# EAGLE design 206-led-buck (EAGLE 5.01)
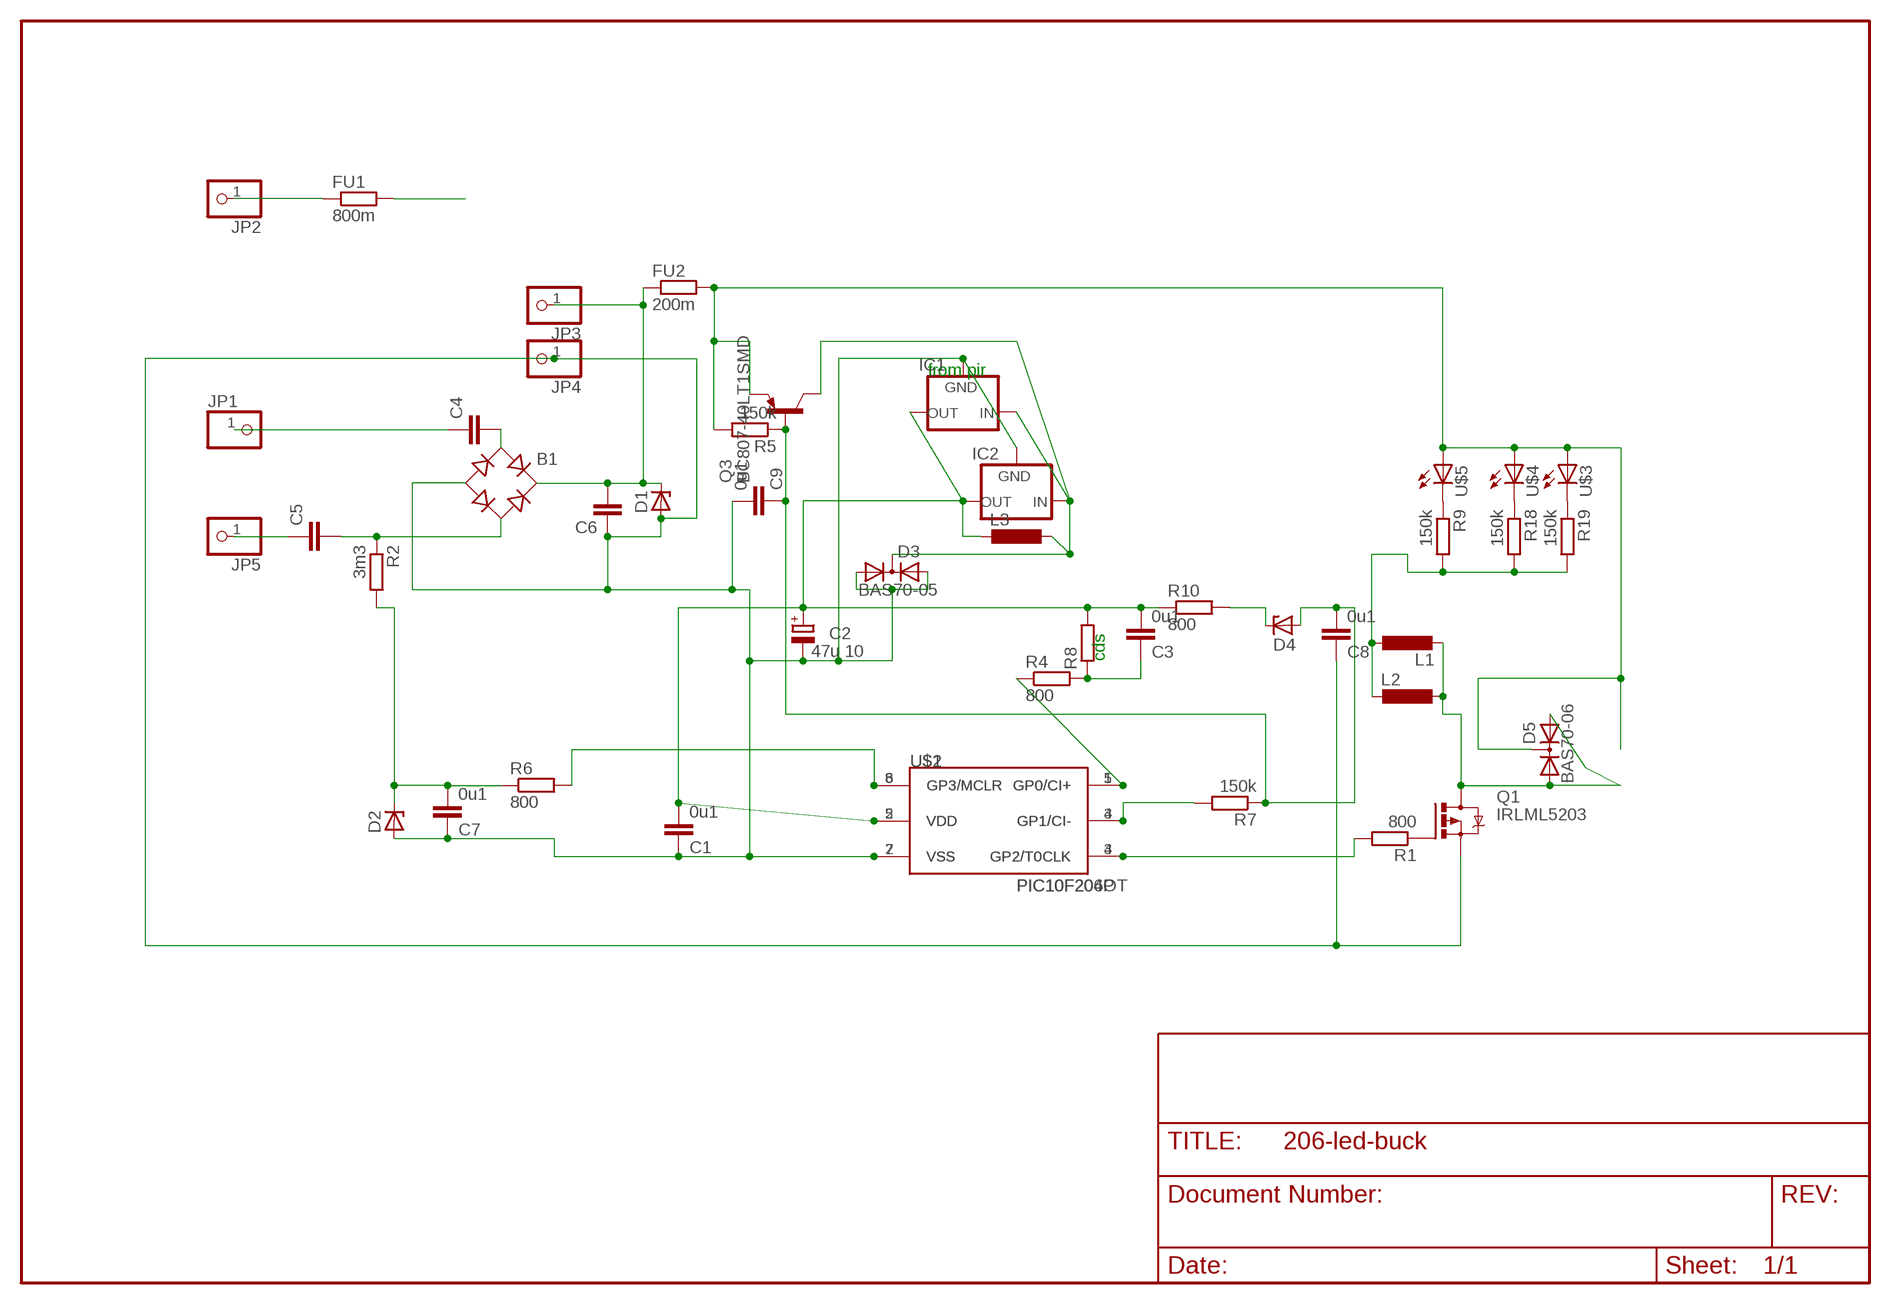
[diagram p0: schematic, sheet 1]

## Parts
B1  RB1A  [RB1A]
C1  0u1  C-EUC1206  [C1206]
C2  47u 10  CPOL-EUE2.5-5  [E2,5-5]
C3  0u1  C-EUC1206  [C1206]
C4  C-EU050-025X075  [C050-025X075]
C5  C-EU050-025X075  [C050-025X075]
C6  C-EU050-025X075  [C050-025X075]
C7  0u1  C-EUC1206  [C1206]
C8  0u1  C-EUC1206  [C1206]
C9  0u1  C-EUC1206  [C1206]
D1  ZENER-DIODEZD-7.5  [ZDIO-7.5]
D2  ZENER-DIODESOT23  [SOT23]
D3  BAS70-05  [SOT23]
D4  ZENER-DIODESOT23  [SOT23]
D5  BAS70-06  [SOT23]
FU1  800m  R-EU_0204/5  [0204/5]
FU2  200m  R-EU_0204/5  [0204/5]
IC1  XC63FPT  [TO92]
IC2  XC63FPP  [SOT89R]
JP1  PINHD-1X1  [1X01]
JP2  PINHD-1X1  [1X01]
JP3  PINHD-1X1  [1X01]
JP4  PINHD-1X1  [1X01]
JP5  PINHD-1X1  [1X01]
L1  L-EUL5650M  [L5650M]
L2  L-EU0207/7  [0207/7]
L3  L-EU0204V  [0204V]
Q1  IRLML5203  [MICRO3]
Q3  BC807-40LT1SMD  [SOT23-BEC]
R1  800  R-EU_R1206  [R1206]
R2  3m3  R-EU_R1206  [R1206]
R4  800  R-EU_R1206  [R1206]
R5  150k  R-EU_R1206  [R1206]
R6  800  R-EU_R1206  [R1206]
R7  150k  R-EU_R1206  [R1206]
R8  R-EU_0207/5V  [0207/5V]
R9  150k  R-EU_R1206  [R1206]
R10  800  R-EU_R1206  [R1206]
R18  150k  R-EU_R1206  [R1206]
R19  150k  R-EU_R1206  [R1206]
U$1  PIC10F206P  [DIL8]
U$2  PIC10F204OT  [SOT23-6]
U$3  LED5MM  [LED5MM]
U$4  LED5MM  [LED5MM]
U$5  LED5MM  [LED5MM]

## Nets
GND: B1.- C1.1 C2.- C6.1 C7.1 C8.1 C9.2 D1.A D2.1(A) D3.1(A1) D3.2(A2) IC1.1(GND) IC2.1(GND) JP4.1 Q1.2(S) U$1.7(VSS) U$2.2(VSS)
N$1: B1.+ C6.2 D1.C FU2.1 JP3.1
N$4: FU1.1 JP2.1
N$6: D4.3(C) R10.2
N$7: D5.3(C) FU2.2 Q3.E R5.2 U$3.A U$4.A U$5.A
N$8: C8.2 C9.1 D4.1(A) Q3.B R5.1 R7.1
N$9: FU1.2
N$10: Q1.1(G) R1.1
N$12: R6.2 U$1.8(GP3/MCLR) U$2.6(GP3/MCLR)
N$13: R7.2 U$1.4(GP1/CI-) U$2.3(GP1/CI-)
N$14: R1.2 U$1.3(GP2/T0CLK) U$2.4(GP2/T0CLK)
N$15: D3.3(C) IC1.2(IN) IC2.2(IN) L3.1 Q3.C
N$16: C7.2 D2.3(C) R2.2 R6.1
N$17: C5.1 JP5.1
N$18: B1.AC2 C5.2 R2.1
N$20: C4.1 JP1.1
N$22: L1.1 L2.2 R9.2 R18.2 R19.2
N$23: C3.1 R4.2 R8.1
N$26: D5.1(A1) D5.2(A2) L1.2 L2.1 Q1.3(D)
N$29: R4.1 U$1.5(GP0/CI+) U$2.1(GP0/CI+)
N$33: B1.AC1 C4.2
N$38: R9.1 U$5.K(C)
N$54: R18.1 U$4.K(C)
N$55: R19.1 U$3.K(C)
V2CC: C1.2 C2.+ C3.2 IC1.3(OUT) IC2.3(OUT) L3.2 R8.2 R10.1 U$1.2(VDD) U$2.5(VDD)

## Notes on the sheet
- from pir
- cds

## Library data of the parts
B1 = rectifier:RB1A: RECTIFIER 1 A
C1 C3-C9 = rcl:C-EU: CAPACITOR, European symbol
C2 = rcl:CPOL-EU: POLARIZED CAPACITOR, European symbol
D1 D2 D4 = diode-1:ZENER-DIODE: Z-Diode
D3 = diode-1:BAS70-05: Silicon Schottky Diodes General-purpose diode for high-speed switching
D5 = diode-1:BAS70-06: Silicon Schottky Diodes General-purpose diode for high-speed switching
FU1 FU2 R1 R2 R4-R7 R9 R10 R18 R19 = rcl:R-EU_: RESISTOR, European symbol
IC1 IC2 = v-reg:XC63FP: Positiv Voltage Regulators www.torex.co.jp/english/product/pro02/pdf/0201_xc62fp.pdf
JP1-JP5 = pinhead:PINHD-1X1: PIN HEADER
L1 = rcl-2:L-EU: INDUCTOR, European symbol
L2 L3 = rcl:L-EU: INDUCTOR, European symbol
Q1 = transistor-power:IRLML5203: HEXFET P-Channel Power MOSFET
Q3 = transistor-pnp:BC807*: PNP Transistror
R8 = rcl(2):R-EU_: RESISTOR, European symbol
U$1 U$2 = microchip-3:PIC10F2*: uPC nW 0,25/0,5k Program Flash memory Comparator
U$3-U$5 = led(3):LED: LED

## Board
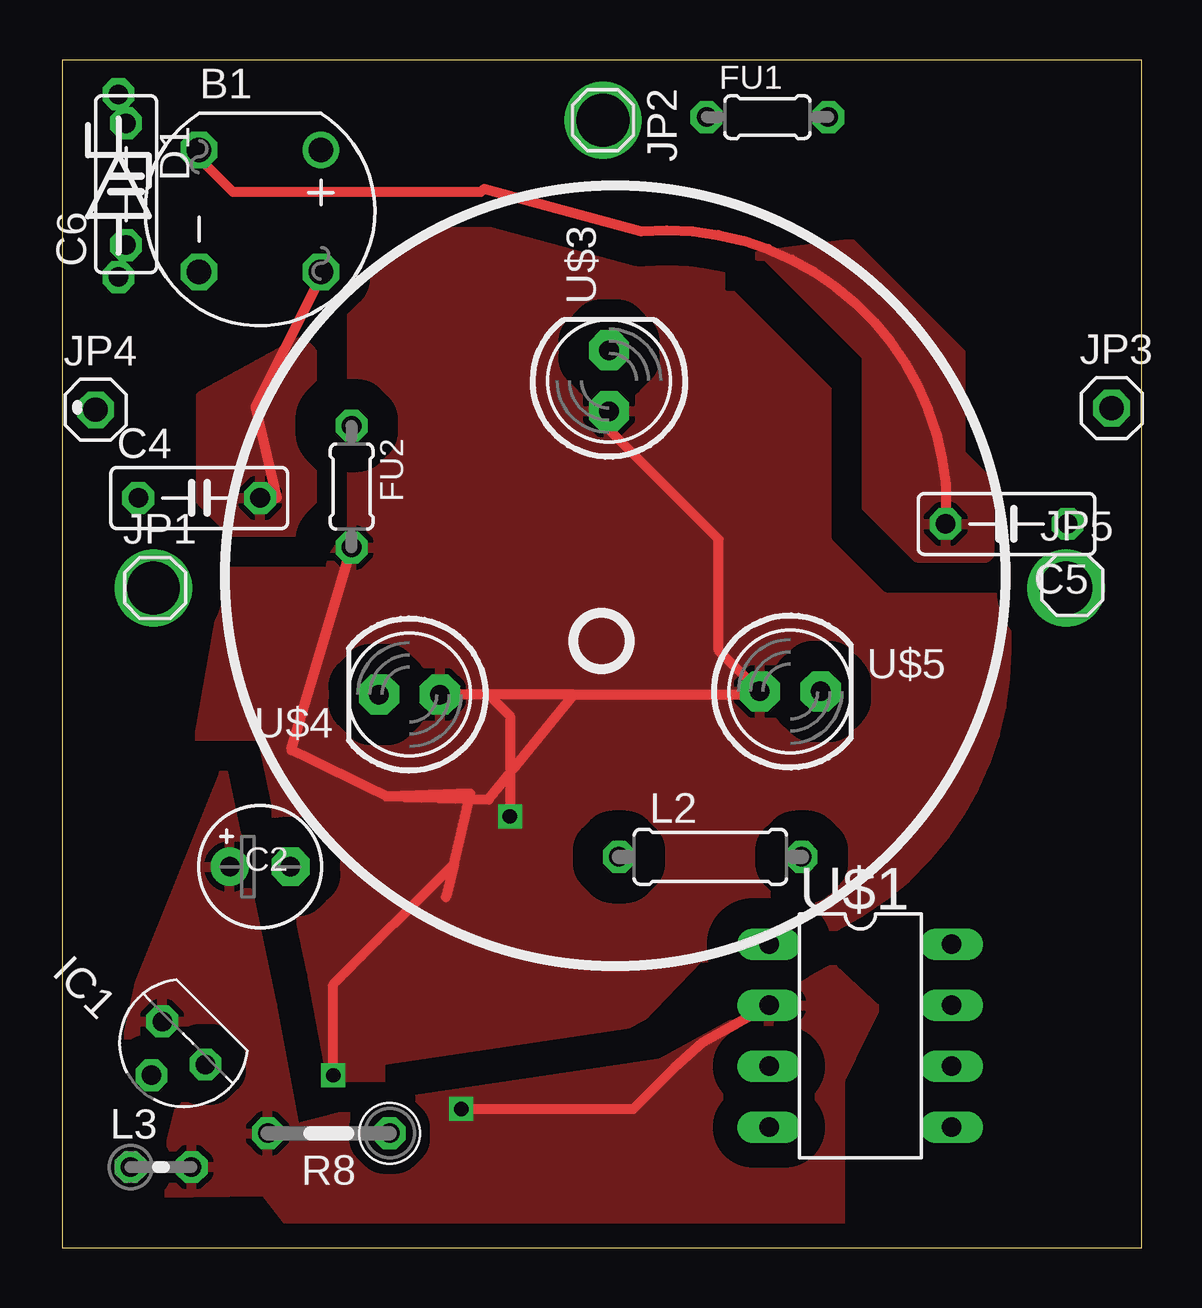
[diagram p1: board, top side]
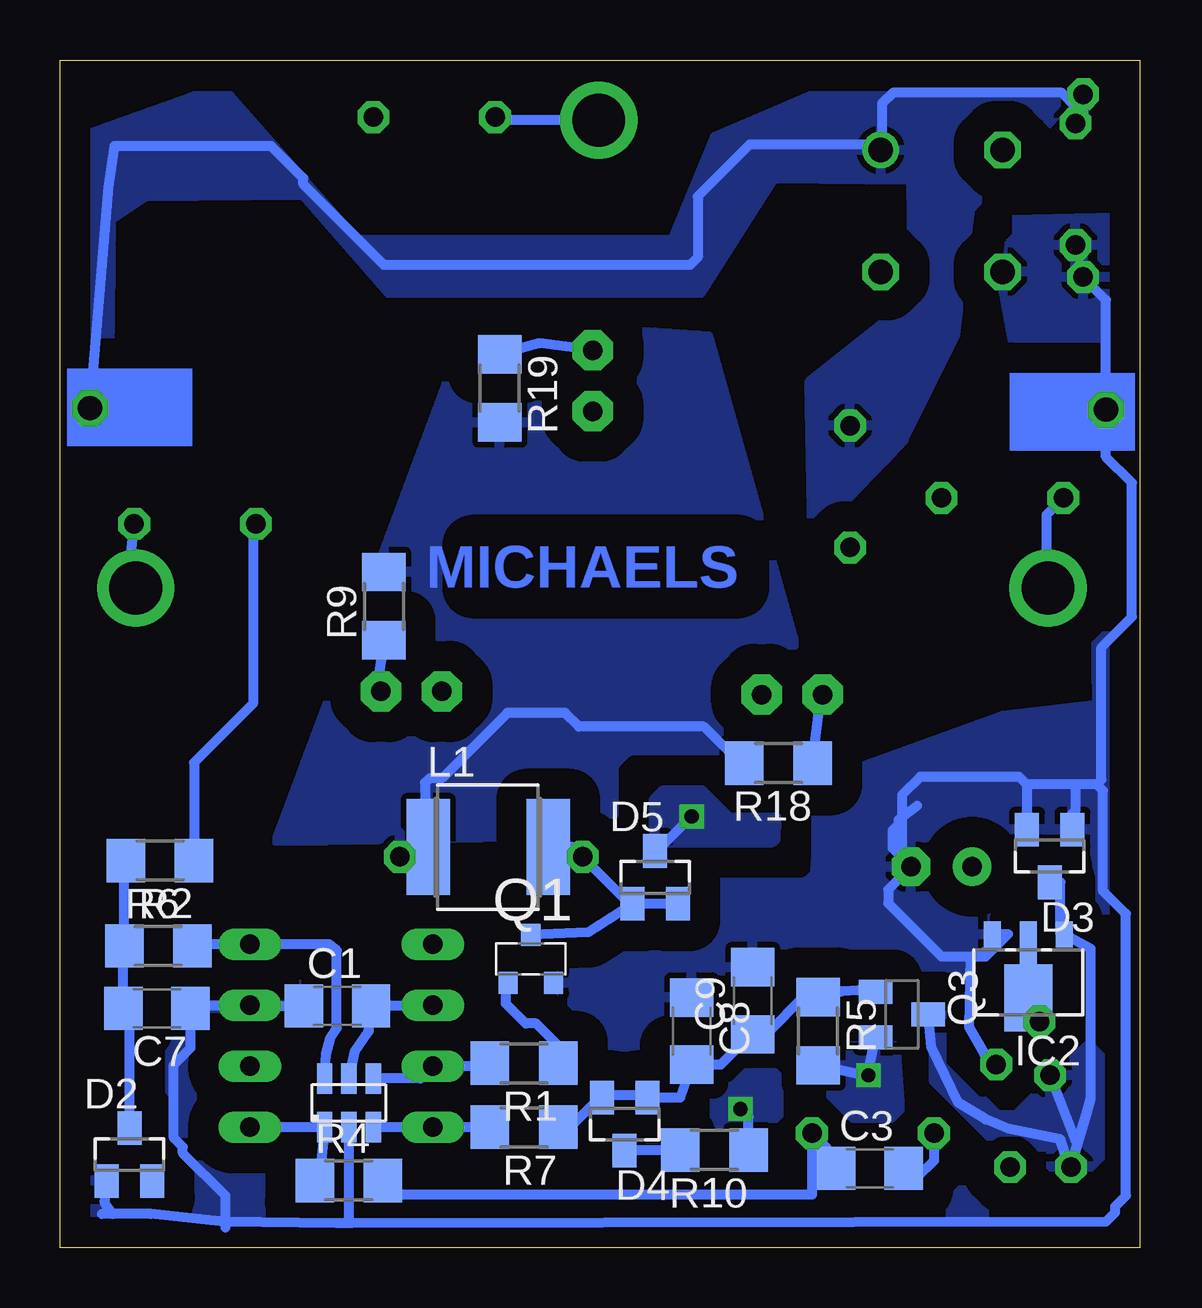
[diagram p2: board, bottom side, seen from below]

Size 45 x 49.5 mm. Coordinates in mm from the lower left corner, seen from the top.
Outline: 0,0 45,0 45,49.5 0,49.5 0,0
Copper layers (1*16): Top 0.035mm / dielectric 1.5mm / Bottom 0.035mm
Design rules "default": minimum track width 10mil, minimum drill 24mil, track to track 8mil, track to pad 8mil, pad to pad 8mil, via to via 8mil, smd to smd 8mil, copper to edge 40mil, drill to drill 8mil, minimum pad ring 10mil, minimum via ring 8mil, stop-mask expansion 4mil, vias tented up to drill 0mil, thermal gap 10mil

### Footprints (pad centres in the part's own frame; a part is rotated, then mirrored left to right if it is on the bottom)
RB1A = drill 1.016 round: + -2.54,2.54 | drill 1.016 octagon: - 2.54,-2.54; AC1 2.54,2.54; AC2 -2.54,-2.54
C1206 = smd 1.6 x 1.8: 1 -1.4,0; 2 1.4,0
E2,5-5 = drill 0.813 pad 1.6 round: + -1.27,0 | drill 0.813 pad 1.6 octagon: - 1.27,0
C050-025X075 = drill 0.813 octagon: 1 -2.54,0; 2 2.54,0
ZDIO-7.5 = drill 0.813 octagon: A 3.81,0; C -3.81,0
SOT23 = smd 1 x 1.4: 1 -0.95,-1.1; 2 0.95,-1.1; 3 0,1.1
0204/5 = drill 0.813 octagon: 1 -2.54,0; 2 2.54,0
TO92 = drill 0.813 octagon: 1 -1.27,0; 2 0,1.905; 3 1.27,0
SOT89R = smd 0.7 x 1.1: 1 1.5,-1.75; 2 -1.5,-1.75 | smd 0.7 x 1.8: 3 0,-1.4 | smd 2 x 2.8: 4 0,0.9
1X01 = drill 1.016 octagon: 1 0,0
L5650M = smd 1.8 x 4: 1 -2.5,0; 2 2.5,0
0207/7 = drill 0.813 octagon: 1 -3.81,0; 2 3.81,0
0204V = drill 0.813 octagon: 1 -1.27,0; 2 1.27,0
MICRO3 = smd 0.8 x 0.9: 1 -0.95,-1; 2 0.95,-1; 3 0,1
SOT23-BEC = smd 1 x 1.4: B -0.95,-1.1; C 0,1.1; E 0.95,-1.1
R1206 = smd 1.6 x 1.803: 1 -1.422,0; 2 1.422,0
0207/5V = drill 0.813 octagon: 1 -2.54,0; 2 2.54,0
DIL8 = drill 0.813 long: 1 -3.81,-3.81; 2 -1.27,-3.81; 3 1.27,-3.81; 4 3.81,-3.81; 5 3.81,3.81; 6 1.27,3.81; 7 -1.27,3.81; 8 -3.81,3.81
SOT23-6 = smd 0.635 x 1.27: 1 -1.016,-1.016; 2 0,-1.016; 3 1.016,-1.016; 4 1.016,1.016; 5 0,1.016; 6 -1.016,1.016
LED5MM = drill 0.813 pad 1.676 octagon: A -1.27,0; K 1.27,0

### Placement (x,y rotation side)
B1  8.25,43.21 270 top
C1  33.43,10.08 0 bottom
C2  8.26,15.88 0 top
C3  11.24,3.3 0 bottom
C4  5.71,31.24 0 top
C5  39.37,30.16 180 top
C6  2.67,44.32 90 top
C7  40.96,9.97 180 bottom
C8  18.67,9.02 270 bottom
C9  16.13,10.29 90 bottom
D1  2.35,44.26 270 top
D2  42.1,3.87 0 bottom
D3  3.75,16.32 180 bottom
D4  21.46,5.14 180 bottom
D5  20.19,15.43 0 bottom
FU1  29.4,47.12 0 top
FU2  12.07,31.72 270 top
IC1  5.07,8.53 135 top
IC2  4.64,11.3 180 bottom
JP1  3.87,27.5 0 top
JP2  22.54,46.99 270 top
JP3  43.75,34.99 0 top
JP4  1.4,34.92 0 top
JP5  42.1,27.62 0 top
L1  27.15,16.69 0 bottom
L2  27.02,16.29 0 top
L3  4.13,3.35 0 top
Q1  25.38,12.03 0 bottom
Q3  9.91,9.72 270 bottom
R1  25.65,7.68 180 bottom
R2  40.83,16.13 180 bottom
R4  32.96,2.79 0 bottom
R5  13.4,9.02 270 bottom
R6  40.89,12.57 0 bottom
R7  25.65,5.02 180 bottom
R8  11.11,4.76 180 top
R9  31.5,26.73 90 bottom
R10  17.72,4.06 180 bottom
R18  15.05,20.19 180 bottom
R19  26.67,35.81 270 bottom
U$1  33.27,8.83 270 top
U$2  32.96,6.03 0 bottom
U$3  22.8,36.13 90 top
U$4  14.48,23.05 180 top
U$5  30.35,23.18 0 top

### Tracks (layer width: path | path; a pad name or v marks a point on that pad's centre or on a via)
GND
  Bottom 0.406: 42.8,1.4 43.13,1.84 D2.1 | 42.8,1.4 43.24,1.4 | 38.16,1.08 33.47,1.02 32.96,1.02 | 38.16,1.08 41.21,1.4 42.8,1.4 | 38.16,1.08 38.1,0.83 38.1,2.16 39.88,3.94 39.88,4.19 40.26,4.57 40.26,7.62 39.56,8.32 C7.1 39.43,10.1 U$1.7 37.06,10.07 C1.1 | IC1.1 6.48,8.07 7.11,9.21 7.05,12.13 | 7.05,12.13 6.03,12.51 6.11,12.45 IC2.1 5.49,13.05 6.41,12.13 7.05,12.13 | 9.27,18.41 10.03,17.84 10.03,17.65 10.29,17.4 10.29,16.64 C2.- | D3.1 2.8,18.09 2.67,18.22 2.67,19.24 2.73,19.3 | 4.7,19.3 D3.2 | 4.7,19.3 5.02,19.62 9.14,19.62 9.91,18.86 9.91,16.26 C2.- | 7.05,12.13 8.26,12.13 10.48,14.35 10.48,14.92 C2.- | 1.78,19.3 2.73,19.3 | 2.73,19.3 4.69,19.3 4.7,19.3 | D1.A 1.4,39.5 JP4.1 1.4,32.96 0.32,31.88 0.32,26.29 1.59,25.02 1.59,19.49 1.78,19.3 | 1.78,19.3 1.52,19.05 1.52,14.86 0.57,13.91 0.57,2.16 1.02,1.71 1.02,1.46 1.4,1.08 32.83,1.02 32.96,1.02 | 32.96,1.02 U$2.2
  pour Bottom (isolate 1.27, rank 5): 0.95,42.93 6.22,42.8 5.21,37.27 1.91,33.02 1.78,22.61 5.71,22.16 13.97,19.18 35.5,17.34 35.43,20.38 45.02,20.26 44.64,0.32 -0.06,0.25
N$1
  Bottom 0.406: JP3.1 42.99,44.2 42.74,45.91 36.2,45.91 34.86,44.58 34.86,44.32 31.5,40.96 18.73,40.96 18.41,41.27 18.41,43.81 16.26,45.97 11.2,45.97 B1.+ 10.73,45.8 10.73,47.69 10.29,48.13 3.24,48.13 2.67,47.56 C6.2 2.35,47.18 D1.C
  pour Bottom (isolate 1.27, rank 2): 1.52,49.34 9.97,49.59 17.72,46.29 19.49,42 32.64,42 38.29,48.39 44.89,46.04 44.7,36.96 42.93,37.08 42.86,42.86 41.4,43.81 34.86,43.88 31.31,39.8 18.29,39.8 15.24,44.58 9.53,44.51 9.46,39.5 13.78,36.07 13.65,29.65 10.67,32.77 9.84,33.66 7.68,38.04 7.05,43.31
N$2  (via drill 2.2)
  other vias: 3.81,27.5
N$3  (via drill 2.2)
  other vias: 41.85,27.5
N$4
  Bottom 0.406: JP2.1 26.73,46.99 FU1.1
N$5  (via drill 2.2)
  other vias: 22.54,46.99
N$6
  Bottom 0.406: D4.3 19.16,4.04 R10.2
N$7  (via drill 0.6)
  Top 0.406: 21.34,23.05 17.78,23.05 | 17.78,23.05 U$4.A | 21.34,23.05 28.96,23.05 U$5.A 27.37,24.89 27.37,29.53 22.8,34.1 U$3.A | FU2.2 9.56,20.73 13.53,18.8 | 13.53,18.8 17.78,18.67 21.34,23.05 | 13.53,18.8 17.02,18.92 16.33,15.99 | 16.33,15.99 16,14.61 | v11.3,7.18 11.3,10.97 16.33,15.99 | v18.67,17.97 18.67,22.16 17.78,23.05
  Bottom 0.406: Q3.E 11.24,7.62 v11.3,7.18 11.52,7.18 R5.2 | D5.3 20.11,16.53 v18.67,17.97
  pour Top (isolate 1.27, rank 3): 21.97,43.56 arc90 6.99,28.57 5.21,18.48 arc90 19.24,4.45 26.54,12.06 arc90 39.37,24.89 39.37,29.02 arc90 24.64,43.75 22.23,43.75
  pour Bottom (isolate 0.61): 15.11,17.91 17.08,17.91 18.22,19.05 19.88,19.05 20.26,18.67 20.26,17.14 20,16.89 15.3,16.89 15.18,17.02
  pour Bottom (isolate 0.61): 10.16,8.38 12.13,8.38 13.02,7.49 13.02,6.48 11.94,5.4 10.35,5.4 9.97,5.78
N$8
  Bottom 0.406: R7.1 23.75,5.02 22.42,6.35 20.75,6.35 D4.1 19.15,6.24 C8.2 17.46,7.62 16.7,8.38 C9.1 15.68,8.95 15.49,8.95 14.01,10.44 R5.1 13.25,10.67 12.45,10.67 11.68,10.73 Q3.B
N$10
  Bottom 0.406: R1.1 24.23,8.42 25.15,9.34 25.59,9.34 26.42,10.16 26.42,10.94 Q1.1
N$12
  Bottom 0.406: U$2.6 33.91,8.06 33.72,8.76 33.47,9.14 33.47,12.38 33.78,12.64 U$1.8 39.41,12.64 R6.2
N$13
  Bottom 0.406: R7.2 U$1.4 U$2.3
N$14
  Bottom 0.406: U$2.4 29.97,7.05 U$1.3 27.2,7.56 R1.2
N$15
  Bottom 0.406: L3.1 2.22,5.52 2.03,6.22 2.03,12.46 IC2.2 3.3,13.05 3.3,15.22 D3.3 | Q3.C 8.68,8.36 7.56,6.03 6.41,5.33 5.46,4.95 3.3,4.51 2.98,3.56 2.6,3.48 L3.1 | L3.1 2.6,4.28 IC1.2
  pour Bottom (isolate 0.61): 8.26,9.78 8.26,7.62 6.73,6.1 6.48,6.1 5.91,5.52 5.14,5.52 3.75,6.92 3.68,6.92 2.22,8.38 2.03,8.38 1.65,8 1.65,3.75 2.48,2.92 3.24,2.92 3.68,3.37 3.68,4.19 5.84,4.19 8.57,6.92 8.57,9.59 8.38,9.78
N$16
  Bottom 0.406: D2.3 42.1,9.71 C7.2 42.36,12.53 R6.1 42.32,16.07 R2.2
N$17
  Bottom 0.406: JP5.1 42.1,28.32 C5.1
N$18
  Top 0.406: B1.AC2 5.52,45.6 7.11,44.01 17.46,44.01 17.59,44.13 24.13,42.35 arc-90 36.83,31.81 C5.2
  Bottom 0.406: R2.1 39.41,20.22 36.96,22.67 36.96,30.04 C5.2
  pour Top (isolate 0.61): 29.02,41.34 29.34,41.34 33.53,37.15 33.53,30.86 35.62,28.77 38.54,28.77 38.67,28.89 38.67,31.88 37.47,33.08 37.47,37.27 32.89,41.85
N$20
  Bottom 0.406: JP1.1 3.87,30.54 C4.1
N$22
  Bottom 0.406: L2.2 30.42,16.69 L1.1 29.78,16.83 29.78,19.37 29.59,19.56 29.08,19.56 26.35,22.29 23.94,22.29 23.37,21.72 18.16,21.72 16.64,20.19 R18.2
  pour Bottom (isolate 1.27, rank 2): 21.97,38.29 28.07,38.23 36,16.95 12.19,17.4 17.97,37.97 21.59,38.23
N$23
  Bottom 0.406: C3.1 13.02,4.13 R8.1 13.65,2.2 31.09,2.2 R4.2
N$26
  Bottom 0.406: Q1.3 22.99,13.14 D5.1 | D5.1 21.26,14.33 L2.1 23.62,16.69 L1.2 | D5.2 D5.1
N$29
  Bottom 0.406: U$1.5 U$2.1 34.16,3.2 R4.1
N$33
  Top 0.406: C4.2 8.95,31.24 8.06,35.05 10.54,39.96 B1.AC1
  pour Top (isolate 1.676): 5.78,35.5 5.78,31.11 7.05,29.84 9.84,29.84 10.41,30.42 10.41,37.34 9.97,37.78
N$38
  Bottom 0.406: U$5.K 31.81,23.18 R9.1
N$54
  Bottom 0.406: R18.1 13.27,22.99 U$4.K
N$55
  Bottom 0.406: U$3.K 25.02,37.69 R19.1
V2CC  (via drill 0.6)
  Top 0.406: v16.64,5.78 23.81,5.78 25.53,7.49 26.73,8.57 U$1.2
  Bottom 0.406: U$2.5 32.7,8.19 32.13,9.02 32.07,9.47 C1.2 32.1,10.1 U$1.2 | C3.2 9.27,2.92 8.57,3.62 R8.2 | R10.1 16.29,5.44 v16.64,5.78 | IC1.3 4.64,9.43 IC2.3
  pour Top (isolate 1.016, rank 2): 6.73,19.75 3.24,11.05 2.54,7.94 2.6,6.29 5.08,6.6 4,2.29 8.45,2.35 9.53,0.95 32.45,0.95 32.45,6.99 33.91,9.97 32.13,11.62 24.96,7.68 13.91,6.03 9.72,4.95 8.76,10.1
  pour Bottom (isolate 0.61): 15.75,4.95 15.62,4.95 15.05,5.52 15.05,7.11 15.43,7.49 17.21,7.49 17.72,6.99 17.72,5.33 17.34,4.95
(copper drawn outside any net)
  shapes: Bottom area x2

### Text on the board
Bottom: MICHAELS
